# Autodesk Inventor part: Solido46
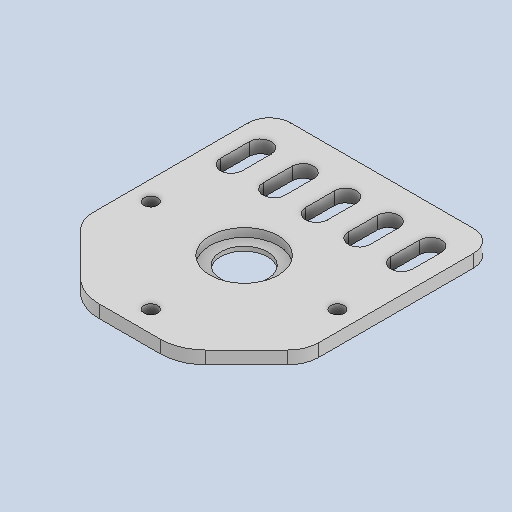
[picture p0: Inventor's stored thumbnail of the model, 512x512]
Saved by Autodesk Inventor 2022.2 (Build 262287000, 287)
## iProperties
Created: 2024-10
Part Number: Solido46
Material: Acciaio
Document SubType Name: Modeling
Designer: 18907419
Density: 7.85 g/cm^3
Appearance: Default
Author: 18907419
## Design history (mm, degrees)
feature "Solido46"
node "Solido1"
